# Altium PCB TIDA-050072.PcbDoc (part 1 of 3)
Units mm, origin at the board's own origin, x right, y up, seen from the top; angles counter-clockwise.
Board outline 125.73 x 87.63 mm, 2 copper layers (Top Layer, Bottom Layer), stack 1.575 mm thick; 105 components, 63 nets, 347 pads, 390 vias.
Unrouted connection lines stored in the file: 6.
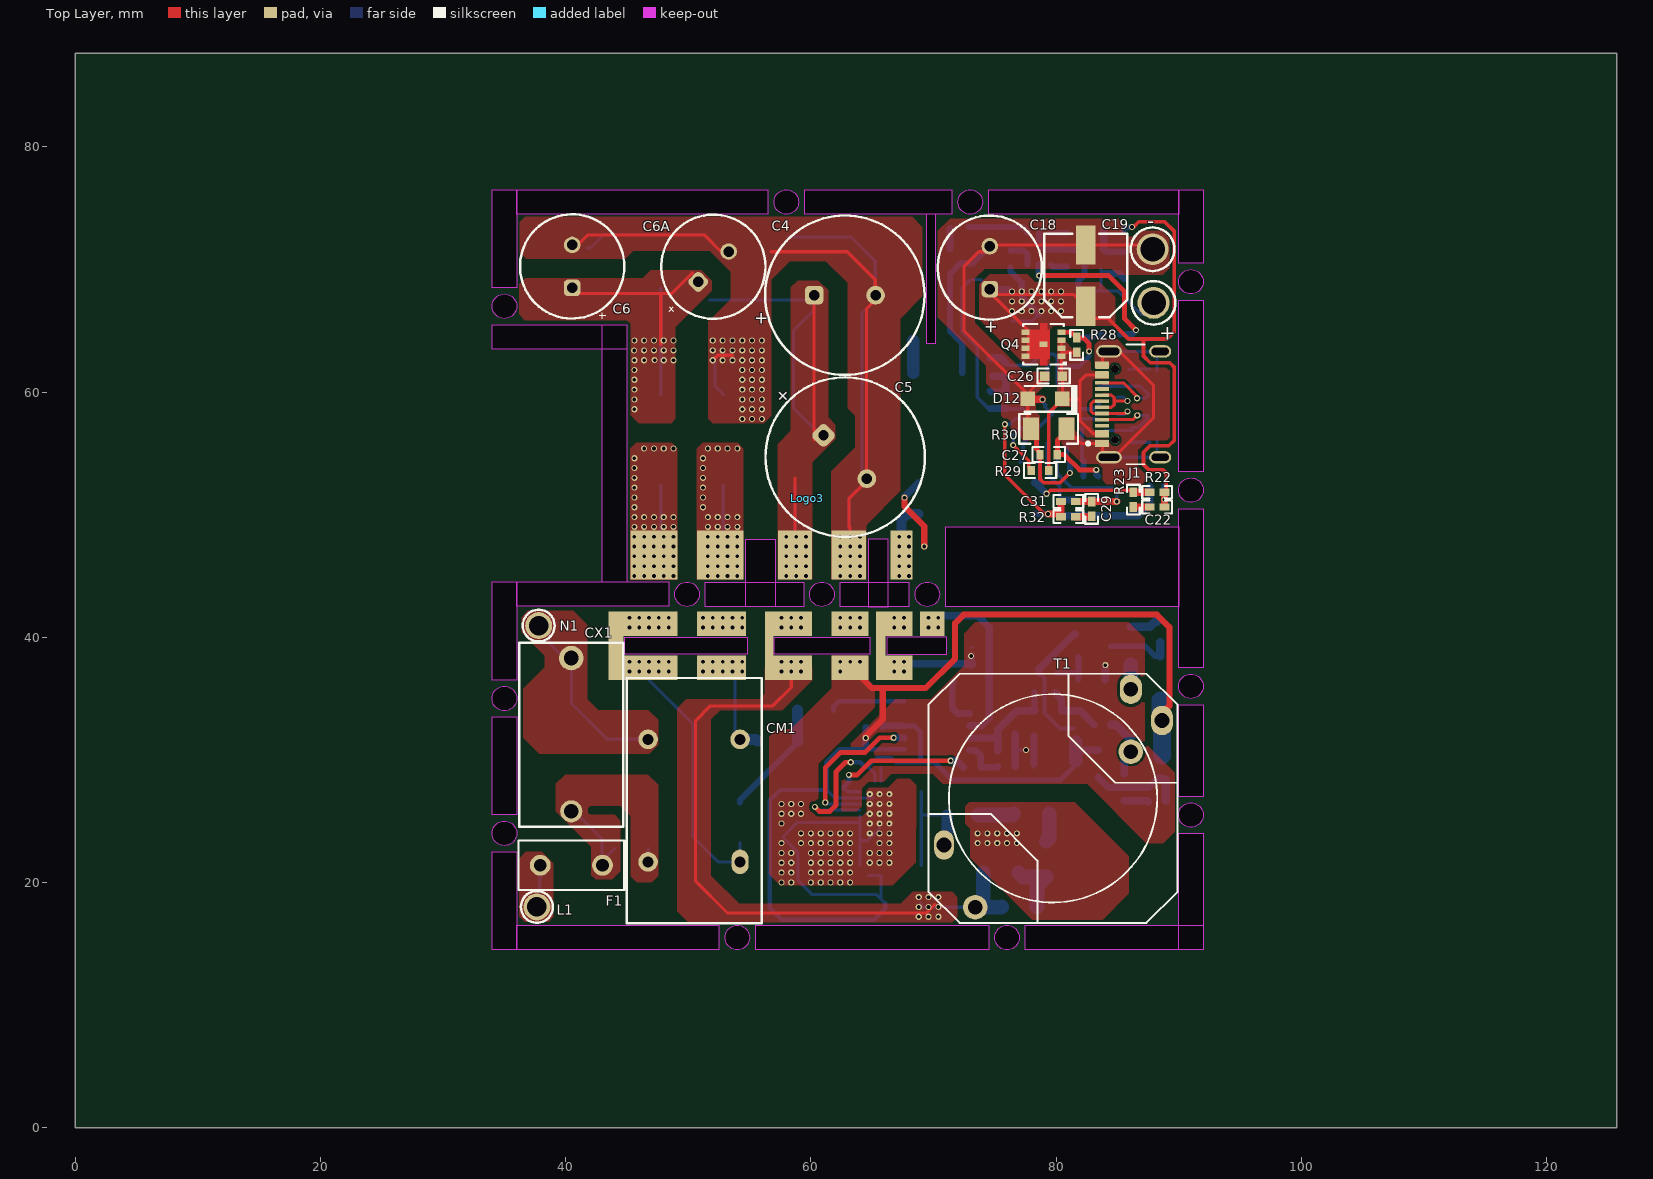
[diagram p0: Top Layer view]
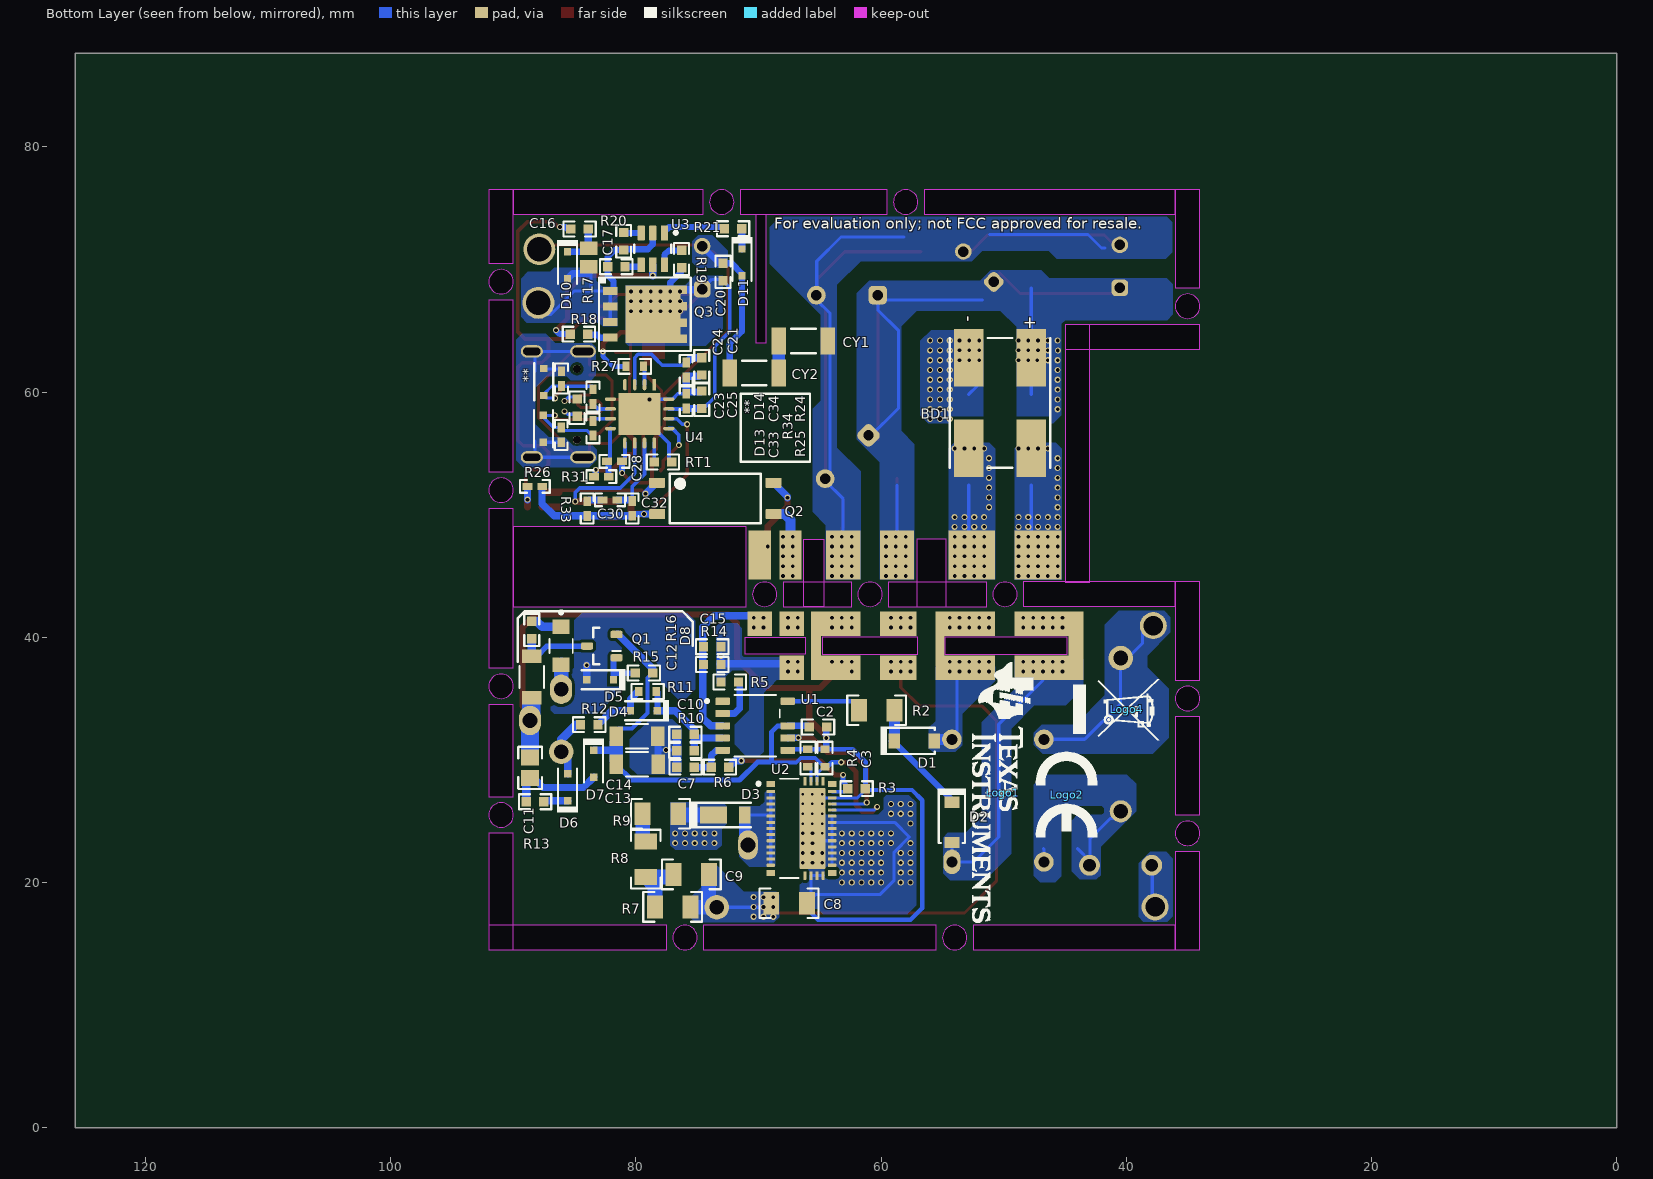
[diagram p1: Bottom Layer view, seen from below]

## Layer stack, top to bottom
Top Solder: solder mask 0.0102, Solder Resist, Dk 3.5
Top Layer: signal copper 0.0356
Dielectric1: core 1.5037, FR-4 High Tg, Dk 4.8
Bottom Layer: signal copper 0.0356
Bottom Solder: solder mask 0.0102, Solder Resist, Dk 3.5

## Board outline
0,0 125.73,0 125.73,87.63 0,87.63
cut-out: 91,35 cw(c91,36) 90,36 cw(c91,36) 91,37 cw(c91,36) 92,36 cw(c91,36)
cut-out: 91,24.5 cw(c91,25.5) 90,25.5 cw(c91,25.5) 91,26.5 cw(c91,25.5) 92,25.5 cw(c91,25.5)
cut-out: 76,14.5 cw(c76,15.5) 75,15.5 cw(c76,15.5) 76,16.5 cw(c76,15.5) 77,15.5 cw(c76,15.5)
cut-out: 54,14.5 cw(c54,15.5) 53,15.5 cw(c54,15.5) 54,16.5 cw(c54,15.5) 55,15.5 cw(c54,15.5)
cut-out: 35,23 cw(c35,24) 34,24 cw(c35,24) 35,25 cw(c35,24) 36,24 cw(c35,24)
cut-out: 35,34 cw(c35,35) 34,35 cw(c35,35) 35,36 cw(c35,35) 36,35 cw(c35,35)
cut-out: 69.5,42.5 cw(c69.5,43.5) 68.5,43.5 cw(c69.5,43.5) 69.5,44.5 cw(c69.5,43.5) 70.5,43.5 cw(c69.5,43.5)
cut-out: 91,51 cw(c91,52) 90,52 cw(c91,52) 91,53 cw(c91,52) 92,52 cw(c91,52)
cut-out: 91,68 cw(c91,69) 90,69 cw(c91,69) 91,70 cw(c91,69) 92,69 cw(c91,69)
cut-out: 35,66 cw(c35,67) 34,67 cw(c35,67) 35,68 cw(c35,67) 36,67 cw(c35,67)
cut-out: 73,74.5 cw(c73,75.5) 72,75.5 cw(c73,75.5) 73,76.5 cw(c73,75.5) 74,75.5 cw(c73,75.5)
cut-out: 58,74.5 cw(c58,75.5) 57,75.5 cw(c58,75.5) 58,76.5 cw(c58,75.5) 59,75.5 cw(c58,75.5)
cut-out: 60.9,42.5 cw(c60.9,43.5) 59.9,43.5 cw(c60.9,43.5) 60.9,44.5 cw(c60.9,43.5) 61.9,43.5 cw(c60.9,43.5)
cut-out: 49.9,42.5 cw(c49.9,43.5) 48.9,43.5 cw(c49.9,43.5) 49.9,44.5 cw(c49.9,43.5) 50.9,43.5 cw(c49.9,43.5)
cut-out: 62.4,42.5 62.4,44.5 68,44.5 68,42.5
cut-out: 92,53.5 90,53.5 90,67.5 92,67.5
cut-out: 45,65.5 45,63.5 34,63.5 34,65.5
cut-out: 36,68.5 34,68.5 34,76.5 36,76.5
cut-out: 59.5,74.5 59.5,76.5 71.5,76.5 71.5,74.5
cut-out: 74.5,16.5 74.5,14.5 55.5,14.5 55.5,16.5
cut-out: 36,25.5 34,25.5 34,33.5 36,33.5
cut-out: 36,14.5 34,14.5 34,22.5 36,22.5
cut-out: 90,34.5 92,34.5 92,27 90,27
cut-out: 90,24 92,24 92,14.5 90,14.5
cut-out: 92,16.5 92,14.5 77.5,14.5 77.5,16.5
cut-out: 52.5,16.5 52.5,14.5 36,14.5 36,16.5
cut-out: 36,36.5 34,36.5 34,44.525 36,44.525
cut-out: 92,37.5 90,37.5 90,50.5 92,50.5
cut-out: 92,70.5 90,70.5 90,76.5 92,76.5
cut-out: 74.5,74.5 74.5,76.5 90,76.5 90,74.5
cut-out: 36,74.5 36,76.5 56.5,76.5 56.5,74.5
cut-out: 51.4,42.5 51.4,44.5 59.4,44.5 59.4,42.5
cut-out: 36,42.521 36,44.521 48.4,44.521 48.4,42.521
cut-out: 43,65.5 45,65.5 45,44.5 43,44.5
cut-out: 69.4,64 70.2,64 70.2,74.5 69.4,74.5
cut-out: 71,49 90,49 90,42.5 71,42.5
cut-out: 66.3,48 64.7,48 64.7,42.5 66.3,42.5
cut-out: 54.7,48 57.1,48 57.1,42.5 54.7,42.5
cut-out: 66.2,40 66.2,38.6 71.1,38.6 71.1,40
cut-out: 64.8,40 64.8,38.6 57,38.6 57,40
cut-out: 54.8,40 54.8,38.6 44.8,38.6 44.8,40

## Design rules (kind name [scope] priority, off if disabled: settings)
AcuteAngle [All] p1: minimum=4.50000000000000E+0001 checktracksonly=FALSE
AssemblyTestPointUsage [All] p1: valid=2
BoardOutlineClearance BoardOutlineClearance_MountingHoles [OnCopper and InComponentClass('Mounting Holes')] p1: gap=1 ignorepadtopadclearanceinfootprint=FALSE
BoardOutlineClearance BoardOutlineClearance_Poly [OnCopper and IsPoly] p2: gap=0.635 ignorepadtopadclearanceinfootprint=FALSE
BoardOutlineClearance [OnCopper and Not InComponentClass('Logo') and not InComponentClass('FiducialMark') and not InRegion(1000,500,4000,800) and not InPoly] p3: gap=1.016 ignorepadtopadclearanceinfootprint=FALSE
Clearance Clearance_1 [(InNet('VBUS') OR InNet('RTN') OR InNet('AUX_QR') OR InNet('AUX_QR'))] p1: gap=0.2 ignorepadtopadclearanceinfootprint=FALSE
Clearance Clearance_Keepouts [((IsTrack Or IsArc) And Not InPoly) And IsFree and IsKeepOut vs ((IsTrack Or IsArc) And Not InPoly) And IsFree and IsKeepOut] p2: gap=0 ignorepadtopadclearanceinfootprint=FALSE
Clearance Clearance_Poly [InPolygon] p3: gap=0.254 ignorepadtopadclearanceinfootprint=TRUE
Clearance Clearance_FiducialMark [IsKeepOut and InComponentClass('FiducialMark') vs IsPad and InComponentClass('FiducialMark')] p4: gap=0 ignorepadtopadclearanceinfootprint=FALSE
Clearance [All] p5: gap=0.2 ignorepadtopadclearanceinfootprint=TRUE
ComponentClearance ComponentClearance_MountingHoles_FiducialMarks [InComponentClass('Mounting Holes') vs InComponentClass('FiducialMark')] p1: gap=1.27 collisioncheckmode=3 verticalgap=0.254 showdistances=FALSE
ComponentClearance ComponentClearance_Shunt [InComponentClass('Header') vs InComponentClass('Shunt')] p2: gap=0 collisioncheckmode=3 verticalgap=0 showdistances=FALSE
ComponentClearance ComponentClearance_Logo [InComponentClass('Logo')] p3: gap=0.762 collisioncheckmode=3 verticalgap=0.254 showdistances=FALSE
ComponentClearance ComponentClearance_ScrewToNut [(HasFootprint('NY PMS 440 0025 PH')) vs (HasFootprint('Keystone_1902C'))] p4: gap=0.127 collisioncheckmode=3 verticalgap=0.254 showdistances=FALSE
ComponentClearance ComponentClearance_MountingHoles [InComponentClass('Mounting Holes')] p5: gap=2.54 collisioncheckmode=3 verticalgap=2540 showdistances=FALSE
ComponentClearance ComponentClearance_SmallPassives [HasFootprint('0201*') or HasFootprint('0402*') or HasFootprint('0508') or HasFootprint('0603*') or HasFootprint('0612') or HasFootprint('0805*') or HasFootprint('0815*') or HasFootprint('0830*') or HasFootprint('1206*') or HasFootprint('1210*') or HasFootprint('1808*') or HasFootprint('1812*') or HasFootprint('1825*') or HasFootprint('2010*') or HasFootprint('2220*') or HasFootprint('2225*') or HasFootprint('2512*') or HasFootprint('2728*') or HasFootprint('3518*') vs HasFootprint('0201*') or HasFootprint('0402*') or HasFootprint('0508') or HasFootprint('0603*') or HasFootprint('0612') or HasFootprint('0805*') or HasFootprint('0815*') or HasFootprint('0830*') or HasFootprint('1206*') or HasFootprint('1210*') or HasFootprint('1808*') or HasFootprint('1812*') or HasFootprint('1825*') or HasFootprint('2010*') or HasFootprint('2220*') or HasFootprint('2225*') or HasFootprint('2512*') or HasFootprint('2728*') or HasFootprint('3518*')] p6: gap=0.38 collisioncheckmode=3 verticalgap=0.254 showdistances=FALSE
ComponentClearance ComponentClearance_THtoSMT [IsThruComponent vs IsSMTComponent] p7: gap=0.762 collisioncheckmode=3 verticalgap=0.762 showdistances=FALSE
ComponentClearance ComponentClearance_THtoTH [IsThruComponent vs IsThruComponent] p8: gap=0.508 collisioncheckmode=3 verticalgap=0.762 showdistances=FALSE
ComponentClearance [All] p9: gap=0.508 collisioncheckmode=3 verticalgap=0.254 showdistances=FALSE
DiffPairsRouting [All] p1: maxlimit=2.54 minlimit=0.254 mostfreqgap=0.254 toplayer_minwidth=0.381 toplayer_maxwidth=0.381 toplayer_prefwidth=0.381 bottomlayer_minwidth=0.381 bottomlayer_maxwidth=0.381 bottomlayer_prefwidth=0.381 maxuncoupledlength=25.4
FabricationTestPointUsage TestPointUsage [All] p1: valid=2 allowmultiple=FALSE
FabricationTestpoint Testpoint [All] p1: side=3 testpointundercomponent=TRUE minsize=1.016 maxsize=2.54 preferedsize=1.524 minholesize=0 maxholesize=1.016 preferedholesize=0.813 testpointgrid=0.025 allowsidetop=TRUE allowsidebottom=TRUE usegrid=TRUE gridtolerance=0
FanoutControl Fanout_LCC [IsLCC] p1: bgadir=Out bgaviamode=Centered fanoutstyle=Auto fanoutdirection=Alternating viagrid=0.025 // Fanout_LCC (Default Rule)
FanoutControl Fanout_BGA [IsBGA] p2: bgadir=Out bgaviamode=Centered fanoutstyle=Auto fanoutdirection=Alternating viagrid=0.025 // Fanout_BGA (Default Rule)
FanoutControl Fanout_Default [All] p4: bgadir=Out bgaviamode=Centered fanoutstyle=Auto fanoutdirection=Alternating viagrid=0.025 // Fanout_Default (Default Rule)
FanoutControl Fanout_Small [(CompPinCount < 5)] p5: bgadir=Out bgaviamode=Centered fanoutstyle=Auto fanoutdirection=OutThenIn viagrid=0.025 // Fanout_Small (Default Rule)
HoleSize [All] p1: absolutevalues=TRUE maxlimit=6.375 minlimit=0.2 maxpercent=80.000 minpercent=20.000
MinimumAnnularRing MinimumAnnularRing_ThermalPadVias [IsVia and InAnyComponent] p1: minimumring=0.15
MinimumAnnularRing [All] p2: minimumring=0.2
MinimumSolderMaskSliver MinimumSolderMaskSliver_Logo [InComponentClass('Logo') vs InComponentClass('Logo')] p1: minsoldermaskwidth=0.018
MinimumSolderMaskSliver [All] p2: minsoldermaskwidth=0.1
PlaneConnect [All] p1: planeconnectstyle=Direct reliefexpansion=0.254 reliefentries=4 reliefconductorwidth=0.254 reliefairgap=0.254
PolygonConnect [All] p1: connectstyle=Direct reliefconductorwidth=0.254 reliefentries=4 polygonreliefangle="90 Angle" airgapwidth=0.254
RoutingVias ThermalPadVias [IsVia and InAnyComponent] p1: holewidth=0.2 width=0.5 viastyle="Through Hole" minholewidth=0.2 minwidth=0.5 maxholewidth=0.33 maxwidth=0.6
RoutingVias [All] p2: holewidth=0.406 width=0.864 viastyle="Through Hole" minholewidth=0.2 minwidth=0.61 maxholewidth=1.016 maxwidth=1.651
SilkToBoardRegionClearance [Not ((IsComment or IsDesignator) And (Hide <> 'False')) and not InRegion(1000,500,4000,800)] p1:
SilkToSilkClearance SilkToSilkClearance_Pb-FreeLogo [(HasFootprint('Pb-Free_Overlay_Medium') OR HasFootprint('Pb-Free_Overlay_Small')) vs (HasFootprint('Pb-Free_Overlay_Medium') OR HasFootprint('Pb-Free_Overlay_Small'))] p1: silktosilkclearance=0
SilkToSilkClearance [All] p2: silktosilkclearance=0.1
SilkToSolderMaskClearance SilkToComponentPadClearance [(IsPad or IsFill or IsRegion) and InAnycomponent] p1: minsilkscreentomaskgap=0.127 clearancetoexposedcopper=TRUE
SilkToSolderMaskClearance "Silk to Solder Mask Opening" [All] p2: minsilkscreentomaskgap=0.1 clearancetoexposedcopper=FALSE
SolderMaskExpansion [All] p1: expansion=0.05 istentingtop=FALSE
UnRoutedNet [All] p1: checkbadconnections=TRUE
Width [All] p1: maxlimit=2.54 minlimit=0.152 preferedwidth=0.254 checkconnectedcopper=TRUE
14 further rules are at their usual default settings.

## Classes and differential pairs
component class NCP1342+LMG3610_QR: + - BD1 C2 C3 C4 C5 C6 C6A C7 C8 C9 C10 C11 C12 C13 C14 C15 C16 C17 C18 C19 CM1 CX1 D1 D2 D3 D4 D5 D6 D7 D8 D10 D11 F1 L1 N1 Q1 Q2 Q3 R2 R3 R4 R5 R6 R7 R8 R9 R10 R11 R12 R13 R14 R15 R16 R17 R18 R19 R20 R21 T1 U1 U2 U3
component class NCP1342+LMG3610_PD_Board: C20 C21 C22 C23 C24 C25 C26 C27 C28 C29 C30 C31 C32 C33 C34 CY1 CY2 D12 D13 D14 J1 Q4 R22 R23 R24 R25 R26 R27 R28 R29 R30 R31 R32 R33 R34 RT1 U4
component class Logo: Logo1
component class NCP1342+LMG3610_Hardware: Logo1 Logo2 Logo3 Logo4

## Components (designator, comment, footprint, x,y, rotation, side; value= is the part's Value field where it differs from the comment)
+ "5010" Keystone5010#1 87.95,67.275 r0 top
- "5010" Keystone5010#1 87.875,71.65 r0 top
BD1 "Z4DGP406L-HF" Z4-D 50.3,59.11 r270 bottom locked value=600V
C2 "GCM188R71E105KA64D" 0603_HV#1 65.15,32.675 r180 bottom value=1uF
C3 "GCM188R71E105KA64D" 0603_HV#2 64.575,30.15 r90 bottom value=1uF
C4 "400LXW39MEFR12.5X20" CY_1250x2000 62.775,67.9 r0 top value=39uF
C5 "400LXW39MEFR12.5X20" CY_1250x2000 62.8,54.7 r315 top value=39uF
C6 "400AX4.7MTA8X9" AX_800x900 40.525,70.25 r90 top value=4.7uF
C6A "400AX4.7MTA8X9" AX_800x900 52.05,70.225 r45 top value=4.7uF
C7 "C0603C101J5GAC" 0603_HV#1 75.95,29.4 r0 bottom value=100pF
C8 "VJ1206Y103KXGAT5Z" 1206 67.511,18.3 r180 bottom value=0.01uF
C9 "GRM31BR73A102KW01L" 1206 75.475,20.65 r0 bottom value=1000pF
C10 "06035A100JAT2A" 0603_HV#1 75.962,32.09 r0 bottom value=10pF
C11 "CC0805KKX5R8BB106" 0805 88.64,29.35 r90 bottom value=10uF
C12 "GRM31CR72A225KA73L" 1206_190 88.515,36.75 r270 bottom value=2.2uF
C13 "C3216X7R1E106K160AE" 1206_190 79.9,29.65 r180 bottom value=10uF
C14 "C3216X7R1E106K160AE" 1206_190 79.904,31.914 r180 bottom value=10uF
C15 "C0603C102J5GACTU" 0603_HV#1 73.775,39.225 r180 bottom value=1000pF
C16 "06031C471KAT2A" 0603_HV#1 84.6,73.3 r180 bottom value=470pF
C17 "GCM188R71E105KA64D" 0603_HV#1 81.6,70.225 r0 bottom value=1uF
C18 "A750KW687M1EAAE016" Chemi-Con_800x1500 74.6,70.15 r90 top value=680uF
C19 "EEH-ZA1E101XP" Panasonic_D8 82.425,69.5 r90 top value=100uF
C20 "C1608X7R1V105K080AC" 0603_HV#1 72.9,69.8 r90 bottom value=1uF
C21 "C1608X7R1V105K080AC" 0603_HV#1 74.636,62.1 r270 bottom value=1uF
C22 "CGA2B2X7R1H472K050BA" 0402 88.25,50.625 r180 top value=4700pF
C23 "GRM155R71H104ME14D" 0402 75.9,59.26 r90 bottom value=0.1uF
C24 "GRM155R71H104ME14D" 0402 75.9,61.8 r270 bottom value=0.1uF
C25 "C1608X7R1V105K080AC" 0603_HV#1 74.636,59.375 r90 bottom value=1uF
C26 "C1608X7R1V105K080AC" 0603_HV#1 79.8,61.3 r180 top value=1uF
C27 "C0603C102K3GACTU" 0603_HV#2 79.4,54.9 r180 top value=1000pF
C28 "GRM155R70J105KA12D" 0402 81.75,54.35 r0 bottom value=1uF
C29 "CGA2B3X7R1H333K050BB" 0402 82.9,50.475 r90 top value=0.033uF
C30 "CGA2B3X7R1H333K050BB" 0402 82.125,51.2 r180 bottom value=0.033uF
C31 "CGA2B3X7R1H333K050BB" 0402 81,51.075 r0 top value=0.033uF
C32 "CGA2B3X7R1H333K050BB" 0402 80.3,50.504 r90 bottom value=0.033uF
C33 "GRM1555C1H271JA01D" 0402 86.1,56.5 r270 bottom value=270pF
C34 "GRM1555C1H271JA01D" 0402 86.075,61.1 r90 bottom value=270pF
CM1 "11mH" CM_20x11_planwire 50.475,26.675 r90 top locked
CX1 "Used in BOM report" Xcap_15x8.5 40.45,32.05 r90 top locked
CY1 "VJ1808Y102KXEAT5Z" 1808_L 66.35,64.175 r180 bottom value=1000pF
CY2 "VJ1808Y102KXEAT5Z" 1808_L 70.35,61.55 r180 bottom value=1000pF
D1 "SM4007PL-TP" SOD-123FL 57.3,31.55 r180 bottom value=1000V
D2 "SM4007PL-TP" SOD-123FL 54.225,24.9 r270 bottom value=1000V
D3 "RS1KLS" PowerDI123 72.4,25.5 r180 bottom locked value=600V
D4 "1N4148WS" SOD-323 79.35,34 r0 bottom value=75V
D5 "MM3Z12VST1G" SOD-323 82.925,36.525 r0 bottom value=12V
D6 "BAV21WS" SOD-323 85.575,27.75 r90 bottom value=250V
D7 "1N4148WS" SOD-323 83.45,29.678 r270 bottom value=75V
D8 "ES1JLW" FP-UF1JLWHRVG_SOD-123-MFG 86.1,39.3 r270 bottom
D10 "BAV21WS" SOD-323 85.589,70.35 r270 bottom value=250V
D11 "BAV21WS" SOD-323 71.35,70.575 r270 bottom value=250V
D12 "PMEG4030ER,115" SOD-123W 79.1,59.45 r180 top value=40V
D13 "PESD24VL1BA,115" SOD-323-Bi 87.55,57 r90 bottom value=24V
D14 "PESD24VL1BA,115" SOD-323-Bi 87.525,60.825 r270 bottom value=24V
F1 "39213150000" FUSE_392 40.46,21.4 r180 top
J1 "629722000214" FP-629722000214_CONN_USB-MFG 87.35,59 r90 top
L1 "5010" Keystone5010#2 37.65,18 r0 top
Logo1 "Texas Instruments" TI_Stacked_Overlay_Small 50.087,27.333 r270 bottom
Logo2 "CE Mark" CE_Mark_5mm 44.875,27.166 r270 bottom
Logo3 "FCC disclaimer" FCC_disclaimer 59.69,51.352 r0 top
Logo4 "WEEE logo" WEEE_Minimum 39.95,34.137 r270 bottom
N1 "5010" Keystone5010#2 37.8,40.95 r0 top
Q1 "BSS169H6327XTSA1" SOT-23 82.786,39.279 r0 bottom value=100V
Q2 "EL1014(TA)-VG" FP-TLP383(GR-TPL,E_SO6-4-MFG 73.525,51.32 r180 bottom
Q3 "BSC070N10NS5ATMA1" PG-TDSON-8 79.275,66.34 r180 bottom value=100V
Q4 "NTTFS5C454NLTAG" Power_WDFN-8 78.975,63.9 r180 top value=40V
R2 "CRCW12061K00JNEA" 1206 60.368,34.05 r0 bottom value=1.0k
R3 "RC0603FR-07240RL" 0603_HV#1 62,27.65 r180 bottom value=240
R4 "RC0603JR-0747KL" 0603_HV#2 65.975,30.15 r90 bottom value=47k
R5 "CRCW0603160KFKEA" 0603_HV#1 72.35,36.35 r0 bottom value=160k
R6 "ERJ-3EKF1001V" 0603_HV#1 73.15,29.4 r0 bottom value=1.00k
R7 "CRCW1206390KJNEA" 1206 77,18 r180 bottom value=390k
R8 "CRCW12067R50JNEA" 1206 79.2,21.9 r270 bottom value=7.5
R9 "CRCW12067R50JNEA" 1206 78,25.6 r180 bottom value=7.5
R10 "RC0603FR-071K8L" 0603_HV#1 75.962,30.75 r180 bottom value=1.80k
R11 "RC0603FR-07330KL" 0603_HV#2 79.05,35.575 r0 bottom value=330k
R12 "RC0603FR-071K8L" 0603_HV#1 83.807,32.868 r0 bottom value=1.80k
R13 "CRCW06034R70JNEA" 0603_HV#1 88.225,26.575 r180 bottom value=4.7
R14 "RC0603FR-0739KL" 0603_HV#1 73.775,37.775 r0 bottom value=39.0k
R15 "CRCW0603470KJNEA" 0603_HV#1 79.35,37.079 r0 bottom value=470k
R16 "CRCW06034R70JNEA" 0603_HV#1 88.5,40.6 r90 bottom value=4.7
R17 "ERJ-6GEYJ120V" 0805L 83.85,70.975 r90 bottom value=12
R18 "CRCW06034R70JNEA" 0603_HV#1 84.65,64.725 r180 bottom value=4.7
R19 "RC0603JR-07300RL" 0603_HV#1 76.275,70.85 r270 bottom value=300
R20 "RC0603JR-0747KL" 0603_HV#1 81,72.3 r90 bottom value=47k
R21 "RC0603JR-07300RL" 0603_HV#1 72.075,73.325 r180 bottom value=300
R22 "CRCW040211K0FKED" 0402 88.25,51.825 r0 top value=11.0k
R23 "CRCW0402499RFKED" 0402 86.3,51.225 r270 top value=499
R24 "MCR01MZPJ470" 0402 83.5,59.625 r270 bottom value=47
R25 "MCR01MZPJ470" 0402 83.5,57.05 r90 bottom value=47
R26 "CRCW040233K0JNED" 0402 88.25,52.3 r0 bottom value=33k
R27 "RC0603JR-0710KL" 0603_HV#2 80.1,62.1 r0 bottom value=10k
R28 "CRCW04021M00JNED" 0402 81.675,63.85 r270 top value=1.0Meg
R29 "CRCW06031K00FKEA" 0603_HV#2 78.7,53.6 r0 top value=1.00k
R30 "CSR1206-0R005F1" 1206 79.4,57 r0 top value=0.005
R31 "CRCW04025K10JNED" 0402 82.825,53.1 r0 bottom value=5.1k
R32 "CRCW04024K70JNED" 0402 81,49.84 r180 top value=4.7k
R33 "CRCW040247K0JNED" 0402 83.975,50.5 r270 bottom value=47k
R34 "CRCW0603100RJNEA" 0603_HV#1 84.8,58.725 r270 bottom value=100
RT1 "NCP18WM224E03RB" 0603_HV#1 77.8,54.3 r180 bottom value=220k
T1 "RM8" RM8 79.75,26.86 r90 top locked
U1 "NCP1342AMAACD1R2G" FP-NCP1342AMAACD1R2G_SOIC9-MFG 70.275,32.775 r180 bottom
U2 "LMG3622REQ" REQ0038A-MFG 66.5,24.4 r180 bottom locked
U3 "MP6908AGJ-Z" FP-MP6908GJ-Z_TSOT23-6-MFG 78.625,71.675 r270 bottom
U4 "WT6636F" FP-WT6636F_QFN16-IPC_B 79.7,58.223 r270 bottom

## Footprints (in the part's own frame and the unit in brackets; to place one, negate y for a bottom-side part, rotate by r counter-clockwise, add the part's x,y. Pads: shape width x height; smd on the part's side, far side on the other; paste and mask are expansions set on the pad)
0402 [mm] "0402 from SM-752 data"
  rect 0.8x0.6 smd: 1(-0.6,0) 2(0.6,0)
  silkscreen extent -1.22,-0.52 1.22,0.52, body extent -0.55,-0.3 0.55,0.3, height 0.6
0603_HV#1 [mil] "Ernesto recommended land pattern.  26 mil between pads."
  rect 30x30 smd: 1(-28,0) 2(28,0)
  silkscreen extent -52,-24 52,24, body extent -34,-19 34,19, height 39
0603_HV#2 [mil] "Ernesto recommended land pattern.  26 mil between pads."
  rect 23.62x30 smd: 1(-28,0) 2(28,0)
  silkscreen extent -52,-24 52,24, body extent -34,-19 34,19, height 39
0805 [mm] "0805 from SM-752 data"
  rect 1.3x1.5 smd: 1(-0.85,0) 2(0.85,0)
  silkscreen extent -1.72,-0.97 1.72,0.97, body extent -1.1,-0.72 1.1,0.72, height 1.45
0805L [mm] "0805 from SM-752 data"
  rect 1.1x1.4 smd: 1(-0.75,0) 2(0.75,0)
  body extent -1.1,-0.72 1.1,0.72, height 1.45
1206 [mm] "1206 from SM-752 data"
  rect 1.3x1.85 smd: 1(-1.45,0) 2(1.45,0)
  silkscreen extent -2.4,-1.21 2.4,1.21, body extent -1.7,-0.9 1.7,0.9, height 1.35
1206_190 [mm] "1206_190"
  rect 1.1x1.6 smd: 1(-1.7,0) 2(1.7,0)
  silkscreen extent -0.9,-1 0.9,1, body extent -1.75,-0.95 1.75,0.95, height 1.9
1808_L [mm] "Chip Capacitor, Body 4.6x2.0mm, IPC High Density"
  rect 1.2x2.2 smd: 1(-2,0) 2(2,0)
  silkscreen extent -1,-1 1,1, body extent -2.47,-1.2 2.47,1.2, height 2.03
AX_800x900 [mm] "TH, 2-Leads, Dia 8mm, Pin Spacing 3.5mm"
  rrect50% 1.35x1.35 hole 0.85: 1(-1.75,0)
  round 1.35 hole 0.85: 2(1.75,0)
  silkscreen extent -4.28,-4.25 4.25,4.25, body extent -4.25,-4.25 4.26,4.25, height 10.51
CE_Mark_5mm [mm] "Minimum text height for CE Mark"
  silkscreen extent -3.5,-2.5 3.5,2.5
Chemi-Con_800x1500 [mm] "TH, 2-Leads, Dia 8mm, Pin Spacing 3.5mm"
  rrect50% 1.35x1.35 hole 0.85: 1(-1.75,0)
  round 1.35 hole 0.85: 2(1.75,0)
  silkscreen extent -4.25,-4.25 4.25,4.25, body extent -4.25,-4.25 4.26,4.25, height 16.51
CM_20x11_planwire [mm]
  round 1.6 hole 0.9: 1(-5,3.75) 2(5,3.75) 3(5,-3.75)
  oval 2x1.4 hole 0.9: 4(-5,-3.75)
  silkscreen extent -10,-5.5 10,5.5
CY_1250x2000 [mm] "Nichicon"
  rrect50% 1.524x1.524 hole 0.85: 1(-2.5,0)
  round 1.524 hole 0.85: 2(2.5,0)
  silkscreen extent -6.5,-6.5 6.5,6.5, body extent -6.52,-6.49 6.49,6.51, height 21.51
FCC_disclaimer [mm]
FP-629722000214_CONN_USB-MFG [mm]
  rrect100% 1x2.1 hole 1.7 slot 0.6 at 0 deg paste-1000 mask+0: 1(-4.32,3.035) 2(4.32,3.035)
  rrect100% 1x1.8 hole 1.4 slot 0.6 at 0 deg paste-1000 mask+0: 3(-4.32,-1.145) 4(4.32,-1.145)
  rrect17% 0.6x1.15 smd paste+0 mask+0: A1-B12(-3.2,3.6) A4-B9(-2.4,3.6) A9-B4(2.4,3.6) A12-B1(3.2,3.6)
  rrect33% 0.3x1.15 smd paste+0 mask+0: A5(-1.25,3.6) A6(-0.25,3.6) A7(0.25,3.6) A8(1.25,3.6) B5(1.75,3.6) B6(0.75,3.6) B7(-0.75,3.6) B8(-1.75,3.6)
  round 0.65 hole 0.65 unplated paste-1000 mask+0: ""(-2.89,2.535) ""(2.89,2.535)
  silkscreen extent -4.89,0.13 4.89,4.86, body extent -4.79,-3.77 4.79,3.94, height 3.46
FP-MP6908GJ-Z_TSOT23-6-MFG [mm]
  rrect17% 1.2x0.6 smd paste+0 mask+0: 1(-1.3,0.95) 2(-1.3,0) 3(-1.3,-0.95) 4(1.3,-0.95) 5(1.3,0) 6(1.3,0.95)
  silkscreen extent -1.45,-1.5 0.33,2, body extent -1.4,-1.45 1.4,1.45, height 1
FP-NCP1342AMAACD1R2G_SOIC9-MFG [mm]
  rrect17% 1.18x0.58 smd paste+0 mask+0: 1(-2.66,2) 2(-2.66,1) 3(-2.66,0) 4(-2.66,-1) 5(-2.66,-2) 6(2.66,-2) 7(2.66,-1) 8(2.66,0) 10(2.66,2)
  silkscreen extent -4.05,-2.5 2,2.5, body extent -3,-2.45 3,2.45, height 1.75
FP-TLP383(GR-TPL,E_SO6-4-MFG [mm]
  rrect13% 1.3x0.8 smd paste+0 mask+0: 1(-4.75,1.27) 3(-4.75,-1.27) 4(4.75,-1.27) 6(4.75,1.27)
  silkscreen extent -3.7,-2.02 3.7,2.02, body extent -5.01,-1.92 5.01,1.92, height 2.3
FP-UF1JLWHRVG_SOD-123-MFG [mm]
  rrect8% 1.2x1.4 smd paste+0 mask+0: 1(-1.55,0) 2(1.55,0)
  silkscreen extent -2.85,-0.95 0.58,0.95, body extent -1.85,-0.9 1.85,0.9, height 1.02
FP-WT6636F_QFN16-IPC_B [mm]
  rect 0.918x0.292 smd paste+0 mask+0: 1(-2.377,1.2)
  oval 0.918x0.292 smd paste+0 mask+0: 2(-2.377,0.4) 3(-2.377,-0.4) 4(-2.377,-1.2) 9(2.377,-1.2) 10(2.377,-0.4) 11(2.377,0.4) 12(2.377,1.2)
  oval 0.292x0.918 smd paste+0 mask+0: 5(-1.2,-2.377) 6(-0.4,-2.377) 7(0.4,-2.377) 8(1.2,-2.377) 13(1.2,2.377) 14(0.4,2.377) 15(-0.4,2.377) 16(-1.2,2.377)
  rect 3.43x3.43 smd paste-1000 mask+0: 17(0,0)
  body extent -2.5,-2.5 2.5,2.5, height 0.8
FUSE_392 [mm] "LITTELFUSE"
  round 1.7 hole 1.05: 1(-2.54,0) 2(2.54,0)
  silkscreen extent -4.32,-2.03 4.32,2.03, body extent -4.25,-2 4.25,2, height 8
Keystone5010#1 [mm] "Keystone Multipurpose loops"
  round 2.6 hole 2: 1(0,0)
  silkscreen extent -1.78,-1.78 1.78,1.78, body extent -1.6,-1.6 1.59,1.59, height 8.1
Keystone5010#2 [mm] "Keystone Multipurpose loops"
  round 2.2 hole 1.6: 1(0,0)
  silkscreen extent -1.3,-1.3 1.3,1.3, body extent -1.6,-1.6 1.59,1.59, height 8.1
Panasonic_D8 [mm] "SMD, 2-Leads, Dia 6.3mm"
  rect 3.2x1.6 smd: 1(-2.5,0) 2(2.5,0)
  silkscreen extent -3.4,-3.4 3.4,3.4, body extent -3.4,-3.4 3.4,3.4, height 8.01
PG-TDSON-8 [mm] "Infineon recommended land pattern"
  rect 1.2x0.65 smd: 1(-2.825,1.905) 2(-2.825,0.635) 3(-2.825,-0.635) 4(-2.825,-1.905)
  rect 0.5x0.7 smd: 5(3.175,-2) 6(3.175,-0.675) 7(3.175,0.675) 8(3.175,2)
  rect 4.5x4.7 smd paste-2.25: 9(0.675,0)
  silkscreen extent -3.74,-3 3.74,3, body extent -3.18,-2.89 3.17,2.9, height 1.1
Power_WDFN-8 [mm] "SMD, 8-Leads, Body 3.3x3.3mm, Pitch 0.65mm"
  rect 0.66x0.42 smd: 1(-1.47,0.975) 2(-1.47,0.325) 3(-1.47,-0.325) 4(-1.47,-0.975) 5(1.47,-0.975) 6(1.47,-0.325) 7(1.47,0.325) 8(1.47,0.975) 9(0,0)
  Top Layer region: 0.25,1.73 -0.32,1.73 -0.32,1.185 -0.5,1.185 -0.5,-1.185 -0.32,-1.185 -0.32,-1.73 0.25,-1.73 0.25,-1.185 1.33,-1.185 1.33,1.185 0.25,1.185
  silkscreen extent -1.9,-1.65 1.65,1.75, body extent -1.65,-1.65 1.65,1.65, height 0.81
PowerDI123 [mm] "Diodes Inc recommended land pattern, document number DS30628 Rev. 6-2"
  rect 2.2x1.4 smd: 1(-1.275,0)
  rect 0.9x1.4 smd: 2(1.275,0)
  silkscreen extent -3.1,-1.09 1.76,1.09, body extent -2.37,-0.96 1.53,0.97, height 1
REQ0038A-MFG [mm]
  rrect20% 0.7x0.5 smd paste-1000 mask+0: 1(-2.5,3.625) 15(-2.5,-3.625) 20(2.5,-3.625) 34(2.5,3.625)
  rrect40% 0.7x0.25 smd paste+0 mask+0: 2(-2.5,3) 3(-2.5,2.5) 4(-2.5,2) 5(-2.5,1.5) 6(-2.5,1) 7(-2.5,0.5) 8(-2.5,0) 9(-2.5,-0.5) 10(-2.5,-1) 11(-2.5,-1.5) 12(-2.5,-2) 13(-2.5,-2.5) 14(-2.5,-3) 21(2.5,-3) 22(2.5,-2.5) 23(2.5,-2) 24(2.5,-1.5) 25(2.5,-1) 26(2.5,-0.5) 27(2.5,0) 28(2.5,0.5) 29(2.5,1) 30(2.5,1.5) 31(2.5,2) 32(2.5,2.5) 33(2.5,3)
  rrect40% 0.25x0.7 smd paste+0 mask+0: 16(0.275,-3.85) 17(0.775,-3.85) 18(1.275,-3.85) 19(1.775,-3.85) 35(1.775,3.85) 36(1.275,3.85) 37(0.775,3.85) 38(0.275,3.85)
  rrect5% 2.1x6.6 smd paste-1000 mask+0: 39(0.9,0)
  silkscreen extent -3.63,-4.05 -0.23,4.05, body extent -2.65,-4 2.65,4, height 1
RM8 [mm] "RM8"
  round 2 / inner round 1.6 / far side round 2 hole 1.2: 1(-8.89,6.35) 4(3.81,-6.35)
  round 1 on Top Overlay: 2(-8.89,3.81) 3(-6.35,3.81) 5(3.81,-8.89) 8(8.89,-3.81) 9(6.35,-3.81) 10(-3.81,6.35) 12(-6.35,8.89)
  oval 2.4x1.8 hole 1.2: 6(6.35,-8.89) 7(8.89,-6.35)
  oval 2.4x1.6 hole 1.2: 11(-3.81,8.89)
  silkscreen extent -10.16,-10.16 10.16,10.16
SOD-123FL [mm] "Copied from SOD-123"
  rect 0.915x1.22 smd: 1(-1.637,0) 2(1.637,0)
  silkscreen extent -2.74,-1.16 1.68,1.16, body extent -1.9,-0.9 1.9,0.9, height 1
SOD-123W [mm] "NXP recommended land pattern"
  rect 1.2x1.2 smd paste-0.05: 1(-1.4,0) 2(1.4,0)
  silkscreen extent -2.64,-1.14 1.68,1.14, body extent -1.85,-0.95 1.85,0.95, height 1.1
SOD-323 [mm] "NXP recommended land pattern"
  rect 0.6x0.6 smd paste-0.05: 1(-1.1,0) 2(1.1,0)
  silkscreen extent -2.06,-0.86 1.53,0.86, body extent -1.3,-0.67 1.3,0.68, height 1.1
SOD-323-Bi [mm] "SOD323, 2-Leads, Body 1.9x1.45mm, No Polarity Mark"
  rect 0.6x0.6 smd paste-0.05: 1(-1.1,0) 2(1.1,0)
  silkscreen extent -1.53,-0.77 1.53,0.77, body extent -1.27,-0.65 1.27,0.65, height 1.02
SOT-23 [mm] "SOT23, 3-Leads, Body 2.9x1.3mm, Pitch 0.95mm, Lead Span 2.5mm, IPC Medium Density"
  rrect50% 1x0.6 smd: 1(-1.2,0.95) 2(-1.2,-0.95) 3(1.2,0)
  silkscreen extent -1.62,-1.5 0.7,1.5, body extent -1.16,-1.45 1.21,1.45, height 1
TI_Stacked_Overlay_Small [mm]
  silkscreen extent -10.63,-2.49 10.63,2.49
WEEE_Minimum [mm] "WEEElie bin"
  silkscreen extent -2.42,-4.38 2.52,2.65
Xcap_15x8.5 [mm] "Xcap_15x8.5"
  round 1.8 hole 1.2: 1(-6.25,0)
  round 2 hole 1.2: 2(6.25,0)
  silkscreen extent -7.5,-4.25 7.5,4.25
Z4-D [mm] "SMD, 4-Leads, Body 8.1x10.5mm"
  rect 4.7x2.4 smd: 1(-3.7,2.55) 2(3.7,2.55) 3(3.7,-2.55) 4(-3.7,-2.55)
  silkscreen extent -5.3,-4.1 5.3,4.1, body extent -5.3,-4.1 5.3,4.1, height 1.56

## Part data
+ - L1 N1: library part CMP-0055147-2, "Test Point, Multipurpose, Red, TH", Color=Red, Manufacturer="Keystone Electronics", Supplier Part Number 1=36-5010-ND
BD1: library part CMP-0029244-3, "Diode, P-N-Bridge, 600 V, 4 A, Z4-D", Manufacturer="Comchip Technology", Value1=4A, Value2=0.95V
C2 C3 C17: library part CMP-0007139-2, "CAP, CERM, 1 uF, 25 V, +/- 10%, X7R, AEC-Q200 Grade 1, 0603", Cap_Case=0603, Manufacturer=MuRata, Supplier Part Number 1=490-10673-1-ND, TempCo=X7R, Tolerance_%=10%, Value1=Unknown, Value2=25V, ValueDisplayed=1uF
C4 C5: library part CMP-0010248-2, "CAP, AL, 39 uF, 400 V, +/- 20%, TH", Cap_Case=12.5x20, Manufacturer=Rubycon, Supplier Part Number 1=1189-400LXW39MEFR12.5X20-ND, Tolerance_%=20%, Value1=Unknown, Value2=400V, ValueDisplayed=39uF
C6 C6A: library part CMP-0009969-1, "CAP, AL, 4.7 uF, 400 V, +/- 20%, TH", Cap_Case=8x9mm, Manufacturer=Rubycon, Supplier Part Number 1=400AX4.7MTA8X9-ND, Tolerance_%=20%, Value1=Unknown, Value2=400V, ValueDisplayed=4.7uF
C7: library part CMP-0006840-3, "CAP, CERM, 100 pF, 50 V, +/- 5%, C0G/NP0, 0603", Cap_Case=0603, Manufacturer=Kemet, Supplier Part Number 1=1414602, TempCo=C0G/NP0, Tolerance_%=5%, Value1=Unknown, Value2=50V, ValueDisplayed=100pF
C8: library part CMP-0009043-2, "CAP, CERM, 0.01 uF, 1000 V, +/- 10%, X7R, 1206", Cap_Case=1206, Manufacturer=Vishay-Vitramon, Supplier Part Number 1=720-1022-1-ND, TempCo=X7R, Tolerance_%=10%, Value1=Unknown, Value2=1000V, ValueDisplayed=0.01uF
C9: library part CMP-0008916-2, "CAP, CERM, 1000 pF, 1000 V, +/- 10%, X7R, 1206", Cap_Case=1206, Manufacturer=MuRata, Supplier Part Number 1=490-3494-1-ND, TempCo=X7R, Tolerance_%=10%, Value1=Unknown, Value2=1000V, ValueDisplayed=1000pF
C10: library part CMP-0006761-4, "CAP, CERM, 10 pF, 50 V, +/- 5%, C0G/NP0, 0603", Cap_Case=0603, Manufacturer=AVX, Supplier Part Number 1=478-1163-1-ND, TempCo=C0G/NP0, Tolerance_%=5%, Value1="0.403 ohm", Value2=50V, ValueDisplayed=10pF
C11: library part CMP-0084177-1, "CAP, CERM, 10 µF, 25 V,+/- 10%, X5R, 0805", Cap_Case=0805, Manufacturer=Yageo, TempCo=X5R, Tolerance_%=10%, Value2=25V, ValueDisplayed=10µF
C12: library part CMP-0008971-1, "CAP, CERM, 2.2 uF, 100 V, +/- 10%, X7R, 1206_190", Cap_Case=1206, Manufacturer=MuRata, Supplier Part Number 1=490-7209-1-ND, TempCo=X7R, Tolerance_%=10%, Value1=Unknown, Value2=100V, ValueDisplayed=2.2uF
C13 C14: library part CMP-00003-1, "CAP, CERM, 10 uF, 25 V, +/- 10%, X7R, 1206_190", Cap_Case=1206, Manufacturer=TDK, Supplier Part Number 1=445-8906-1-ND, TempCo=X7R, Tolerance_%=10%, Value1=Unknown, Value2=25V, ValueDisplayed=10uF
C15: library part CMP-0006843-4, "CAP, CERM, 1000 pF, 50 V, +/- 5%, C0G/NP0, 0603", Cap_Case=0603, Manufacturer=Kemet, Supplier Part Number 1=399-3293-1-ND, TempCo=C0G/NP0, Tolerance_%=5%, Value1=Unknown, Value2=50V, ValueDisplayed=1000pF
C16: library part CMP-0006744-2, "CAP, CERM, 470 pF, 100 V, +/- 10%, X7R, 0603", Cap_Case=0603, Manufacturer=AVX, Supplier Part Number 1=478-1197-1-ND, TempCo=X7R, Tolerance_%=10%, Value1="0.397 ohm", Value2=100V, ValueDisplayed=470pF
C18: library part CMP-0010407-1, "CAP ALUM POLY 680UF 20% 25V T/H", Cap_Case=8x15, Manufacturer=KEMET, Supplier Part Number 1=399-A750KW687M1EAAE016-ND, Tolerance_%=20%, Value1=Unknown, Value2=25V, ValueDisplayed=680uF
C19: library part CMP-0860234-1, "CAP, Aluminum Polymer, 100 µF, 25 V,+/- 20%, 0.03 ohm, AEC-Q200 Grade 2, D6.3xL7.7mm SMD", Cap_Case=6.3x7.7mm, Manufacturer=Panasonic, Tolerance_%=20%, Value1="0.03 ohm", Value2=25V, ValueDisplayed=100µF
C20 C21 C25 C26: library part CMP-0007052-2, "CAP, CERM, 1 uF, 35 V, +/- 10%, X7R, 0603", Cap_Case=0603, Manufacturer=TDK, Supplier Part Number 1=445-7414-1-ND, TempCo=X7R, Tolerance_%=10%, Value1=Unknown, Value2=35V, ValueDisplayed=1uF
C22: library part CMP-0006321-1, "CAP, CERM, 4700 pF, 50 V, +/- 10%, X7R, AEC-Q200 Grade 1, 0402", Cap_Case=0402, Manufacturer=TDK, Supplier Part Number 1=445-5607-1-ND, TempCo=X7R, Tolerance_%=10%, Value1="0.413508 ohm", Value2=50V, ValueDisplayed=4700pF
C23 C24: library part CMP-0006675-1, "CAP, CERM, 0.1 uF, 50 V, +/- 20%, X7R, 0402", Cap_Case=0402, Manufacturer=MuRata, Supplier Part Number 1=490-10701-1-ND, TempCo=X7R, Tolerance_%=20%, Value1=Unknown, Value2=50V, ValueDisplayed=0.1uF
C27: library part CMP-0006846-1, "CAP, CERM, 1000 pF, 25 V, +/- 10%, C0G/NP0, 0603", Cap_Case=0603, Manufacturer=Kemet, Supplier Part Number 1=399-7833-1-ND, TempCo=C0G/NP0, Tolerance_%=10%, Value1="0 ohm", Value2=25V, ValueDisplayed=1000pF
C28: library part CMP-0064947-2, "CAP, CERM, 1 uF, 6.3 V,+/- 10%, X7R, 0402", Cap_Case=0402, Manufacturer=MuRata, Supplier Part Number 1=490-10024-1-ND, TempCo=X7R, Tolerance_%=10%, Value1=Unknown, Value2=6.3V, ValueDisplayed=1uF
C29 C30 C31 C32: library part CMP-0006329-1, "CAP, CERM, 0.033 uF, 50 V, +/- 10%, X7R, AEC-Q200 Grade 1, 0402", Cap_Case=0402, Manufacturer=TDK, Supplier Part Number 1=445-6896-1-ND, TempCo=X7R, Tolerance_%=10%, Value1="0.098477 ohm", Value2=50V, ValueDisplayed=0.033uF
C33 C34: library part CMP-0006445-1, "CAP, CERM, 270 pF, 50 V, +/- 5%, C0G/NP0, 0402", Cap_Case=0402, Manufacturer=MuRata, Supplier Part Number 1=490-1294-1-ND, TempCo=C0G/NP0, Tolerance_%=5%, Value1=Unknown, Value2=50V, ValueDisplayed=270pF
CM1: library part CM_Choke_Planar, Alternate Manufacturer=-, Manufacturer="Used in BOM report"
CX1: library part CX, Alternate Manufacturer=-
CY1 CY2: library part CMP-0009539-1, "CAP, CERM, 1000 pF, 500 V, +/- 10%, X7R, 1808", Cap_Case=1808, Manufacturer=Vishay-Vitramon, Supplier Part Number 1=720-1061-1-ND, TempCo=X7R, Tolerance_%=10%, Value1=Unknown, Value2=500V, ValueDisplayed=1000pF
D1 D2: library part CMP-0077021-2, "Diode, Standard Recovery Rectifier, 1000 V, 1 A, SOD-123FL", Manufacturer="Micro Commercial Components", Value1=1A, Value2=1.1V
D3: library part CMP-0076978-2, "Diode, Standard Recovery Rectifier, 600 V, 1 A, PowerDI123", Manufacturer="Diodes Inc.", Value1=1A, Value2=1.1V
D4 D7: library part CMP-0079597-2, "Diode, Switching, 75 V, 0.15 A, AEC-Q101, SOD-323", Manufacturer="Diodes Inc.", Value1=0.15A, Value2=1.25V
D5: library part CMP-0085757-1, "Diode, Zener, 12 V, 300 mW, SOD-323", Manufacturer="ON Semiconductor", Power_W=300mW, Value1=0.3W
D6 D10 D11: library part CMP-0029165-1, "Diode, Switching, 250 V, 0.25 A, AEC-Q101, SOD-323", Manufacturer="Diodes Inc.", Supplier Part Number 1=BAV21WS-FDICT-ND, Value1=0.25A, Value2=1.25V
D8: library part CMP-0090530-1, "Diode Standard 600V 1A Surface Mount SOD-123W", Digikey Part Number=UF1JLWHRVGCT-ND, Forward Current=1A, Manufacturer="Taiwan Semiconductor", Max Surge Forward Current=30A, Mouser Part Number=821-UF1JLWHRVG, Operating Temperature Range="-55°C to +150°C", Peak Reverse Current=1uA, ValueDisplayed=15pF
D12: library part CMP-0080763-2, "Diode, Schottky, 40 V, 3 A, AEC-Q101, SOD-123W", Manufacturer=Nexperia, Value1=3A, Value2=0.54V
D13 D14: library part CMP-0006061-5, "Diode, TVS, Bi, 24 V, 70 Vc, SOD323", Manufacturer="NXP Semiconductor", Value1=200W
F1: library part CMP-0003561-1, "Fuse, 3.15 A, 250VAC/VDC, TH", Irating_A=3.15A, Manufacturer=Littelfuse, Supplier Part Number 1=F5504CT-ND
J1: library part CMP-0095999-1, "Conenctor USB 2.0 Type C Horizontal SMT", Current_A=5A, Manufacturer="Wurth Electronics", Operating Temperature Range="-40°C to +85°C", Voltage_V=20V
Logo1: library part CMP-0074838-1, "Texas Instrument Corporate Signature"
Logo2: library part CMP-0074844-1
Logo3: library part CMP-0074847-1, "FCC_disclaimer"
Logo4: library part CMP-0074769-1
Q1: library part CMP-0000949-3, "MOSFET, N-CH, Depletion Mode, 100 V, 0.17 A, AEC-Q101, SOT-23", Alternate Manufacturer=None, Manufacturer="Infineon Technologies", Supplier Part Number 1="BSS169 H6327-ND", Value2="2.1 nC"
Q2: library part CMP-0087394-2, "Optoisolator Transistor Output 5000Vrms 1 Channel 6-SO", Manufacturer=Toshiba
Q3: library part CMP-0000935-1, "MOSFET, N-CH, 100 V, 80 A, PG-TDSON-8", Alternate Manufacturer=None, Manufacturer="Infineon Technologies", Supplier Part Number 1=BSC070N10NS5ATMA1CT-ND, Value2="30 nC"
Q4: library part CMP-0000732-1, "MOSFET, N-CH, 40 V, 20 A, 8-PowerWDFN", Alternate Manufacturer=None, Manufacturer="ON Semiconductor", Supplier Part Number 1=NTTFS5C454NLTAGOSCT-ND, Value1=0, Value2="18 nC"
R2: library part CMP-0018603-1, "RES, 1.0 k, 5%, 0.25 W, 1206", Manufacturer=Vishay-Dale, Power_W=250mW, Supplier Part Number 1=541-1.0KECT-ND, TempCo="200 ppm/C", Tolerance_%=5%, Value2=0.25W, Value_Code=1k00, ValueDisplayed=1.0k
R3: library part CMP-0022938-5, "RES, 240, 1%, 0.1 W, 0603", Manufacturer=Yageo, Power_W=100mW, Supplier Part Number 1=311-240HRCT-ND, TempCo="100 ppm/C", Tolerance_%=1%, Value2=0.1W, Value_Code=240R, ValueDisplayed=240
R4 R20: library part CMP-0025925-5, "RES, 47 k, 5%, 0.1 W, 0603", Manufacturer=Yageo, Power_W=100mW, Supplier Part Number 1=311-47KGRCT-ND, TempCo="100 ppm/C", Tolerance_%=5%, Value2=0.1W, Value_Code=47k0, ValueDisplayed=47k
R5: library part CMP-0022072-1, "RES, 160 k, 1%, 0.1 W, 0603", Manufacturer=Vishay-Dale, Power_W=100mW, Supplier Part Number 1=541-160KHCT-ND, TempCo="100 ppm/C", Tolerance_%=1%, Value2=0.1W, Value_Code=160k
R6: library part CMP-0022680-2, "RES, 1.00 k, 1%, 0.1 W, 0603", Manufacturer=Panasonic, Power_W=100mW, Supplier Part Number 1=P1.00KHCT-ND, TempCo="100 ppm/C", Tolerance_%=1%, Value2=0.1W, Value_Code=1k00, ValueDisplayed=1.00k
R7: library part CMP-0018664-2, "RES, 390 k, 5%, 0.25 W, 1206", Manufacturer=Vishay-Dale, Power_W=250mW, Supplier Part Number 1=541-390KECT-ND, TempCo="200 ppm/C", Tolerance_%=5%, Value2=0.25W, Value_Code=390k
